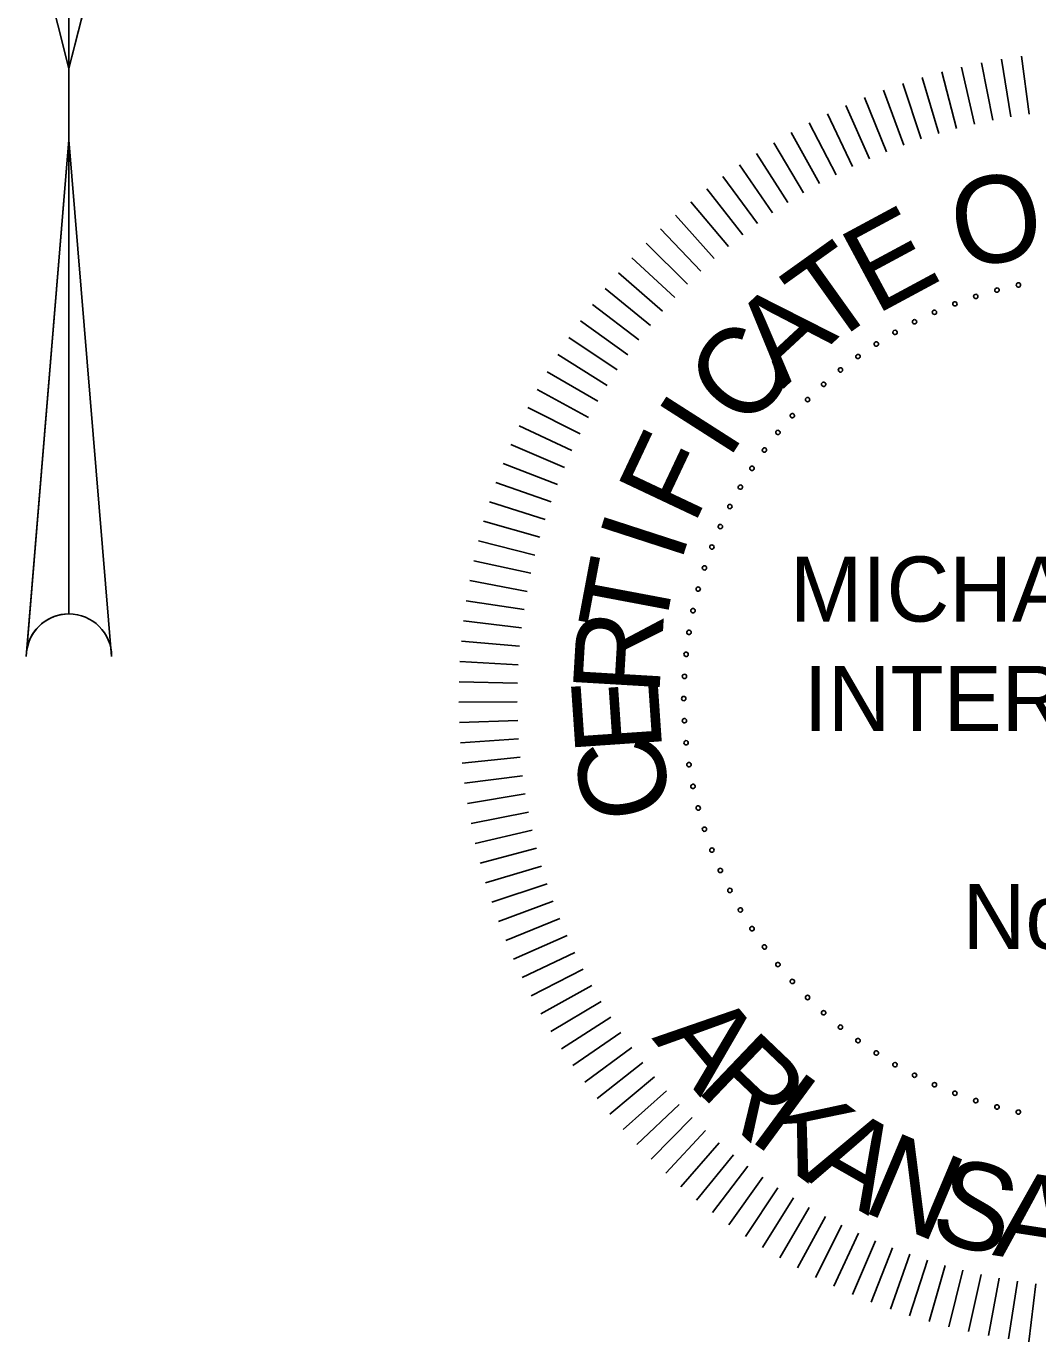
# Model space of a CAD drawing. Extents: x 309348 to 309445, y 336383 to 336484.
# Drawn here: x 309373.486 to 309375.43, y 336386.623 to 336389.15 of the extents above; entities that cross this region are included whole.
import ezdxf

# ---------------------------------------------------------------- set-up
doc = ezdxf.new("R2010")
doc.units = 0
doc.layers.add('G-ANNO-TEXT', color=7, linetype='Continuous')
doc.layers.add('R_Annotation', color=7, linetype='Continuous')

msp = doc.modelspace()

# ---------------------------------------------------------------- linework, layer by layer
at = {"layer": 'G-ANNO-TEXT'}
for points in [[(309375.3433, 336388.9694), (309375.3217, 336389.0795)], [(309375.3217, 336389.0795), (309375.3433, 336388.9694)], [(309375.3783, 336388.9757), (309375.3602, 336389.0865)], [(309375.3602, 336389.0865), (309375.3783, 336388.9757)], [(309375.4135, 336388.9809), (309375.3988, 336389.0922)], [(309375.3988, 336389.0922), (309375.4135, 336388.9809)], [(309375.274, 336388.9535), (309375.2455, 336389.0621)], [(309375.2455, 336389.0621), (309375.274, 336388.9535)], [(309375.3086, 336388.962), (309375.2835, 336389.0714)], [(309375.2835, 336389.0714), (309375.3086, 336388.962)], [(309375.2058, 336388.9333), (309375.1706, 336389.0398)], [(309375.1706, 336389.0398), (309375.2058, 336388.9333)], [(309375.2398, 336388.9439), (309375.2079, 336389.0515)], [(309375.2079, 336389.0515), (309375.2398, 336388.9439)], [(309375.139, 336388.9088), (309375.0971, 336389.0129)], [(309375.0971, 336389.0129), (309375.139, 336388.9088)], [(309375.1722, 336388.9216), (309375.1336, 336389.027)], [(309375.1336, 336389.027), (309375.1722, 336388.9216)], [(309375.0739, 336388.8802), (309375.0256, 336388.9815)], [(309375.0256, 336388.9815), (309375.0739, 336388.8802)], [(309375.1063, 336388.895), (309375.0611, 336388.9978)], [(309375.0611, 336388.9978), (309375.1063, 336388.895)], [(309375.0421, 336388.8644), (309374.9906, 336388.9641)], [(309374.9906, 336388.9641), (309375.0421, 336388.8644)], [(309375.0107, 336388.8476), (309374.9561, 336388.9456)], [(309374.9561, 336388.9456), (309375.0107, 336388.8476)], [(309374.9497, 336388.811), (309374.8891, 336388.9055)], [(309374.8891, 336388.9055), (309374.9497, 336388.811)], [(309374.9799, 336388.8298), (309374.9223, 336388.9261)], [(309374.9223, 336388.9261), (309374.9799, 336388.8298)], [(309374.9201, 336388.7913), (309374.8565, 336388.8838)], [(309374.8565, 336388.8838), (309374.9201, 336388.7913)], [(309374.8911, 336388.7707), (309374.8246, 336388.8612)], [(309374.8628, 336388.7492), (309374.7935, 336388.8375)], [(309374.7935, 336388.8375), (309374.8628, 336388.7492)], [(309374.8352, 336388.7268), (309374.7631, 336388.8129)], [(309374.7631, 336388.8129), (309374.8352, 336388.7268)], [(309374.8082, 336388.7036), (309374.7336, 336388.7873)], [(309374.7336, 336388.7873), (309374.8082, 336388.7036)], [(309374.7821, 336388.6795), (309374.7048, 336388.7609)], [(309374.7048, 336388.7609), (309374.7821, 336388.6795)], [(309374.7567, 336388.6546), (309374.6769, 336388.7335)], [(309374.6769, 336388.7335), (309374.7567, 336388.6546)], [(309374.7321, 336388.6289), (309374.6498, 336388.7053)], [(309374.6498, 336388.7053), (309374.7321, 336388.6289)], [(309374.7083, 336388.6025), (309374.6237, 336388.6762)], [(309374.6237, 336388.6762), (309374.7083, 336388.6025)], [(309374.6853, 336388.5753), (309374.5984, 336388.6464)], [(309374.5984, 336388.6464), (309374.6853, 336388.5753)], [(309374.6632, 336388.5474), (309374.5742, 336388.6157)], [(309374.5742, 336388.6157), (309374.6632, 336388.5474)], [(309374.642, 336388.5189), (309374.5509, 336388.5843)], [(309374.5509, 336388.5843), (309374.642, 336388.5189)], [(309374.6217, 336388.4896), (309374.5286, 336388.5522)], [(309374.5286, 336388.5522), (309374.6217, 336388.4896)], [(309374.6024, 336388.4598), (309374.5073, 336388.5194)], [(309374.5073, 336388.5194), (309374.6024, 336388.4598)], [(309374.584, 336388.4294), (309374.4871, 336388.486)], [(309374.4871, 336388.486), (309374.584, 336388.4294)], [(309374.5665, 336388.3984), (309374.4679, 336388.4519)], [(309374.4679, 336388.4519), (309374.5665, 336388.3984)], [(309374.5501, 336388.3669), (309374.4498, 336388.4173)], [(309374.4498, 336388.4173), (309374.5501, 336388.3669)], [(309374.5346, 336388.3348), (309374.4328, 336388.3821)], [(309374.4328, 336388.3821), (309374.5346, 336388.3348)], [(309374.5201, 336388.3023), (309374.4169, 336388.3463)], [(309374.4169, 336388.3463), (309374.5201, 336388.3023)], [(309374.5067, 336388.2694), (309374.4021, 336388.3101)], [(309374.4021, 336388.3101), (309374.5067, 336388.2694)], [(309374.4943, 336388.2361), (309374.3885, 336388.2735)], [(309374.3885, 336388.2735), (309374.4943, 336388.2361)], [(309374.483, 336388.2024), (309374.3761, 336388.2364)], [(309374.3761, 336388.2364), (309374.483, 336388.2024)], [(309374.4727, 336388.1683), (309374.3648, 336388.199)], [(309374.3648, 336388.199), (309374.4727, 336388.1683)], [(309374.4635, 336388.1339), (309374.3547, 336388.1612)], [(309374.3547, 336388.1612), (309374.4635, 336388.1339)], [(309374.4554, 336388.0993), (309374.3458, 336388.1232)], [(309374.3458, 336388.1232), (309374.4554, 336388.0993)], [(309374.4484, 336388.0644), (309374.338, 336388.0849)], [(309374.338, 336388.0849), (309374.4484, 336388.0644)], [(309374.4425, 336388.0294), (309374.3315, 336388.0463)], [(309374.3315, 336388.0463), (309374.4425, 336388.0294)], [(309374.4377, 336387.9941), (309374.3262, 336388.0076)], [(309374.3262, 336388.0076), (309374.4377, 336387.9941)], [(309374.4339, 336387.9588), (309374.3222, 336387.9687)], [(309374.3222, 336387.9687), (309374.4339, 336387.9588)], [(309374.4314, 336387.9233), (309374.3193, 336387.9297)], [(309374.3193, 336387.9297), (309374.4314, 336387.9233)], [(309374.4299, 336387.8877), (309374.3177, 336387.8906)], [(309374.3177, 336387.8906), (309374.4299, 336387.8877)], [(309374.4295, 336387.8522), (309374.3173, 336387.8516)], [(309374.3173, 336387.8516), (309374.4295, 336387.8522)], [(309374.4303, 336387.8166), (309374.3181, 336387.8125)], [(309374.3181, 336387.8125), (309374.4303, 336387.8166)], [(309374.4321, 336387.7811), (309374.3202, 336387.7734)], [(309374.3202, 336387.7734), (309374.4321, 336387.7811)], [(309374.4351, 336387.7457), (309374.3235, 336387.7345)], [(309374.3235, 336387.7345), (309374.4351, 336387.7457)], [(309374.4392, 336387.7103), (309374.328, 336387.6956)], [(309374.328, 336387.6956), (309374.4392, 336387.7103)], [(309374.4444, 336387.6752), (309374.3337, 336387.657)], [(309374.3337, 336387.657), (309374.4444, 336387.6752)], [(309374.4508, 336387.6401), (309374.3406, 336387.6185)], [(309374.3406, 336387.6185), (309374.4508, 336387.6401)], [(309374.4582, 336387.6054), (309374.3488, 336387.5803)], [(309374.3488, 336387.5803), (309374.4582, 336387.6054)], [(309374.4667, 336387.5708), (309374.3581, 336387.5423)], [(309374.3581, 336387.5423), (309374.4667, 336387.5708)], [(309374.4762, 336387.5366), (309374.3686, 336387.5047)], [(309374.3686, 336387.5047), (309374.4762, 336387.5366)], [(309374.4869, 336387.5026), (309374.3803, 336387.4674)], [(309374.3803, 336387.4674), (309374.4869, 336387.5026)], [(309374.4986, 336387.469), (309374.3932, 336387.4304)], [(309374.3932, 336387.4304), (309374.4986, 336387.469)], [(309374.5113, 336387.4358), (309374.4072, 336387.394)], [(309374.4072, 336387.394), (309374.5113, 336387.4358)], [(309374.5251, 336387.4031), (309374.4224, 336387.3579)], [(309374.4224, 336387.3579), (309374.5251, 336387.4031)], [(309374.54, 336387.3707), (309374.4387, 336387.3224)], [(309374.4387, 336387.3224), (309374.54, 336387.3707)], [(309374.5558, 336387.3389), (309374.4561, 336387.2874)], [(309374.4561, 336387.2874), (309374.5558, 336387.3389)], [(309374.5726, 336387.3075), (309374.4746, 336387.2529)], [(309374.4746, 336387.2529), (309374.5726, 336387.3075)], [(309374.5904, 336387.2767), (309374.4941, 336387.2191)], [(309374.4941, 336387.2191), (309374.5904, 336387.2767)], [(309374.6091, 336387.2465), (309374.5147, 336387.1859)], [(309374.5147, 336387.1859), (309374.6091, 336387.2465)], [(309374.6288, 336387.2169), (309374.5364, 336387.1533)], [(309374.5364, 336387.1533), (309374.6288, 336387.2169)], [(309374.6495, 336387.1879), (309374.559, 336387.1214)], [(309374.559, 336387.1214), (309374.6495, 336387.1879)], [(309374.671, 336387.1596), (309374.5827, 336387.0903)], [(309374.5827, 336387.0903), (309374.671, 336387.1596)], [(309374.6934, 336387.132), (309374.6073, 336387.0599)], [(309374.6073, 336387.0599), (309374.6934, 336387.132)], [(309374.7166, 336387.105), (309374.6328, 336387.0304)], [(309374.6328, 336387.0304), (309374.7166, 336387.105)], [(309374.7407, 336387.0789), (309374.6593, 336387.0016)], [(309374.6593, 336387.0016), (309374.7407, 336387.0789)], [(309374.7656, 336387.0535), (309374.6867, 336386.9737)], [(309374.6867, 336386.9737), (309374.7656, 336387.0535)], [(309374.7913, 336387.0289), (309374.7149, 336386.9466)], [(309374.7149, 336386.9466), (309374.7913, 336387.0289)], [(309374.744, 336386.9205), (309374.8177, 336387.0051)], [(309374.8177, 336387.0051), (309374.744, 336386.9205)], [(309374.7738, 336386.8952), (309374.8449, 336386.9821)], [(309374.8449, 336386.9821), (309374.7738, 336386.8952)], [(309374.8045, 336386.871), (309374.8728, 336386.96)], [(309374.8728, 336386.96), (309374.8045, 336386.871)], [(309374.8359, 336386.8477), (309374.9013, 336386.9388)], [(309374.9013, 336386.9388), (309374.8359, 336386.8477)], [(309374.868, 336386.8254), (309374.9305, 336386.9185)], [(309374.9305, 336386.9185), (309374.868, 336386.8254)], [(309374.9008, 336386.8041), (309374.9604, 336386.8992)], [(309374.9604, 336386.8992), (309374.9008, 336386.8041)], [(309374.9342, 336386.7839), (309374.9908, 336386.8808)], [(309374.9908, 336386.8808), (309374.9342, 336386.7839)], [(309374.9683, 336386.7647), (309375.0218, 336386.8633)], [(309375.0218, 336386.8633), (309374.9683, 336386.7647)], [(309375.0029, 336386.7466), (309375.0533, 336386.8469)], [(309375.0533, 336386.8469), (309375.0029, 336386.7466)], [(309375.0381, 336386.7296), (309375.0853, 336386.8314)], [(309375.0853, 336386.8314), (309375.0381, 336386.7296)], [(309375.0738, 336386.7137), (309375.1178, 336386.8169)], [(309375.1178, 336386.8169), (309375.0738, 336386.7137)], [(309375.11, 336386.6989), (309375.1508, 336386.8035)], [(309375.1508, 336386.8035), (309375.11, 336386.6989)], [(309375.1467, 336386.6853), (309375.1841, 336386.7911)], [(309375.1841, 336386.7911), (309375.1467, 336386.6853)], [(309375.1837, 336386.6729), (309375.2178, 336386.7798)], [(309375.2178, 336386.7798), (309375.1837, 336386.6729)], [(309375.2212, 336386.6616), (309375.2519, 336386.7695)], [(309375.2519, 336386.7695), (309375.2212, 336386.6616)], [(309375.2589, 336386.6515), (309375.2862, 336386.7603)], [(309375.2862, 336386.7603), (309375.2589, 336386.6515)], [(309375.297, 336386.6426), (309375.3209, 336386.7522)], [(309375.3209, 336386.7522), (309375.297, 336386.6426)], [(309375.3353, 336386.6348), (309375.3557, 336386.7452)], [(309375.3557, 336386.7452), (309375.3353, 336386.6348)], [(309375.3739, 336386.6283), (309375.3908, 336386.7393)], [(309375.3908, 336386.7393), (309375.3739, 336386.6283)], [(309375.4126, 336386.623), (309375.4261, 336386.7345)], [(309375.4261, 336386.7345), (309375.4126, 336386.623)]]:
    msp.add_lwpolyline(points, dxfattribs=at)
for centre, start, end in [((309375.3928, 336388.6529), 12, 192), ((309375.3928, 336388.6529), 192, 12), ((309375.3107, 336388.6309), 18, 198), ((309375.3107, 336388.6309), 198, 18), ((309375.3515, 336388.643), 15, 195), ((309375.3515, 336388.643), 195, 15), ((309375.2314, 336388.6004), 24, 204), ((309375.2314, 336388.6004), 204, 24), ((309375.2706, 336388.6167), 21, 201), ((309375.2706, 336388.6167), 201, 21), ((309375.193, 336388.5821), 27, 207), ((309375.193, 336388.5821), 207, 27), ((309375.1556, 336388.5618), 30, 210), ((309375.1556, 336388.5618), 210, 30), ((309375.1194, 336388.5396), 33, 213), ((309375.1194, 336388.5396), 213, 33), ((309375.0843, 336388.5155), 36, 216), ((309375.0843, 336388.5155), 216, 36), ((309375.0506, 336388.4897), 39, 219), ((309375.0506, 336388.4897), 219, 39), ((309375.0183, 336388.462), 42, 222), ((309375.0183, 336388.462), 222, 42), ((309374.9874, 336388.4328), 45, 225), ((309374.9874, 336388.4328), 225, 45), ((309374.9581, 336388.4019), 48, 228), ((309374.9581, 336388.4019), 228, 48), ((309374.9305, 336388.3696), 51, 231), ((309374.9305, 336388.3696), 231, 51), ((309374.9046, 336388.3359), 54, 234), ((309374.9046, 336388.3359), 234, 54), ((309374.8806, 336388.3008), 57, 237), ((309374.8806, 336388.3008), 237, 57), ((309374.8583, 336388.2646), 60, 240), ((309374.8583, 336388.2646), 240, 60), ((309374.8381, 336388.2272), 63, 243), ((309374.8381, 336388.2272), 243, 63), ((309374.8198, 336388.1888), 66, 246), ((309374.8198, 336388.1888), 246, 66), ((309374.8035, 336388.1495), 69, 249), ((309374.8035, 336388.1495), 249, 69), ((309374.7893, 336388.1095), 72, 252), ((309374.7893, 336388.1095), 252, 72), ((309374.7772, 336388.0687), 75, 255), ((309374.7772, 336388.0687), 255, 75), ((309374.7673, 336388.0273), 78, 258), ((309374.7673, 336388.0273), 258, 78), ((309374.7595, 336387.9855), 81, 261), ((309374.7595, 336387.9855), 261, 81), ((309374.754, 336387.9434), 84, 264), ((309374.754, 336387.9434), 264, 84), ((309374.7507, 336387.901), 87, 267), ((309374.7507, 336387.901), 267, 87), ((309374.7495, 336387.8585), 90, 270), ((309374.7495, 336387.8585), 270, 90), ((309374.7507, 336387.816), 93, 273), ((309374.7507, 336387.816), 273, 93), ((309374.754, 336387.7736), 96, 276), ((309374.754, 336387.7736), 276, 96), ((309374.7595, 336387.7314), 99, 279), ((309374.7595, 336387.7314), 279, 99), ((309374.7673, 336387.6896), 102, 282), ((309374.7673, 336387.6896), 282, 102), ((309374.7772, 336387.6483), 105, 285), ((309374.7772, 336387.6483), 285, 105), ((309374.7893, 336387.6075), 108, 288), ((309374.7893, 336387.6075), 288, 108), ((309374.8035, 336387.5674), 111, 291), ((309374.8035, 336387.5674), 291, 111), ((309374.8198, 336387.5282), 114, 294), ((309374.8198, 336387.5282), 294, 114), ((309374.8381, 336387.4898), 117, 297), ((309374.8381, 336387.4898), 297, 117), ((309374.8583, 336387.4524), 120, 300), ((309374.8583, 336387.4524), 300, 120), ((309374.8806, 336387.4162), 123, 303), ((309374.8806, 336387.4162), 303, 123), ((309374.9046, 336387.3811), 126, 306), ((309374.9046, 336387.3811), 306, 126), ((309374.9305, 336387.3474), 129, 309), ((309374.9305, 336387.3474), 309, 129), ((309374.9581, 336387.3151), 132, 312), ((309374.9581, 336387.3151), 312, 132), ((309374.9874, 336387.2842), 135, 315), ((309374.9874, 336387.2842), 315, 135), ((309375.0183, 336387.2549), 138, 318), ((309375.0183, 336387.2549), 318, 138), ((309375.0506, 336387.2273), 141, 321), ((309375.0506, 336387.2273), 321, 141), ((309375.0843, 336387.2015), 144, 324), ((309375.0843, 336387.2015), 324, 144), ((309375.1194, 336387.1774), 147, 327), ((309375.1194, 336387.1774), 327, 147), ((309375.1556, 336387.1552), 330, 150), ((309375.1556, 336387.1552), 150, 330), ((309375.193, 336387.1349), 153, 333), ((309375.193, 336387.1349), 333, 153), ((309375.2314, 336387.1166), 156, 336), ((309375.2314, 336387.1166), 336, 156), ((309375.2706, 336387.1003), 159, 339), ((309375.2706, 336387.1003), 339, 159), ((309375.3107, 336387.0861), 162, 342), ((309375.3107, 336387.0861), 342, 162), ((309375.3515, 336387.074), 165, 345), ((309375.3515, 336387.074), 345, 165), ((309375.3928, 336387.0641), 168, 348), ((309375.3928, 336387.0641), 348, 168)]:
    msp.add_arc(centre, 0.00417, start, end, dxfattribs=at)
at = {"layer": 'R_Annotation'}
for p, q in [((309373.5677, 336389.0687), (309373.6316, 336389.3211)), ((309373.5677, 336389.3148), (309373.5677, 336388.2645)), ((309373.5677, 336389.3148), (309373.5677, 336389.0687)), ((309373.5677, 336388.9316), (309373.4868, 336387.9526)), ((309373.5677, 336388.0212), (309373.5677, 336388.9316))]:
    msp.add_line(p, q, dxfattribs=at)
for points in [[(309373.6316, 336389.3211), (309373.5677, 336389.0687), (309373.5038, 336389.3211)], [(309373.6497, 336387.9391), (309373.5677, 336388.9316), (309373.4857, 336387.9391)]]:
    msp.add_lwpolyline(points, dxfattribs=at)
for start, end in [(0, 180), (90, 170.5511)]:
    msp.add_arc((309373.5677, 336387.9391), 0.082, start, end, dxfattribs=at)

# ---------------------------------------------------------------- texts
at = {"layer": 'G-ANNO-TEXT'}
for s, rotation, p in [('O', 10.7295, (309375.2801, 336388.6817)), ('E', 28.279, (309375.1182, 336388.5944)), ('T', 35.5725, (309375.0252, 336388.5299)), ('A', 42.8659, (309374.9406, 336388.4529)), ('C', 50.1594, (309374.8704, 336388.3696)), ('I', 57.4529, (309374.8342, 336388.3139)), ('F', 64.7464, (309374.7688, 336388.1892)), ('I', 72.0398, (309374.743, 336388.116)), ('T', 79.3333, (309374.7099, 336387.9724)), ('R', 86.6268, (309374.7022, 336387.8622)), ('E', 93.9203, (309374.7084, 336387.7581)), ('C', 101.2137, (309374.7297, 336387.6421)), ('A', 309.5859, (309374.687, 336387.2058)), ('R', 316.3356, (309374.7698, 336387.1076)), ('K', 323.6428, (309374.8717, 336387.0129)), ('A', 330.3925, (309374.9759, 336386.9377)), ('N', 337.1422, (309375.0882, 336386.8752)), ('S', 344.4494, (309375.2171, 336386.823)), ('A', 351.1991, (309375.3412, 336386.7897))]:
    msp.add_text(s, height=0.1667, rotation=rotation, dxfattribs=at).set_placement(p)
for s, height, p in [('MICHAEL BAKER', 0.125016, (309374.9534, 336388.0063)), (' INTERNATIONAL', 0.125016, (309374.9333, 336387.796)), (' No. 1126', 0.12502, (309375.239, 336387.3775))]:
    msp.add_text(s, height=height, dxfattribs=at).set_placement(p)

doc.saveas('drawing.dxf')
